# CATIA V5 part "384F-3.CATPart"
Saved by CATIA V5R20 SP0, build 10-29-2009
Part number: 384F-3
Source: Unknown
Property "ARTICLENO": "384F-3"
Property "BOMINFO": "384F-3"
Property "CODE": "384F-3"
Property "CREATOR": "CADENAS GmbH"
Property "D1": "28.000"
Property "D2": "38.000"
Property "ELASTOMER": "Ø125-Ø140"
Property "K": "24.000"
Property "L": "100.000"
Property "L1": "15.000"
Property "L2": "45.000"
Property "LINA": "384F-3"
Property "M": "20.000"
Property "NB": "384F-3"
Property "NBSYN": "$CODE."
Property "NN": "384F"
Property "NT": "Pin for Elastomer Springs"
Property "R": "5.000"
Property "SUPPLIER": "CF"
Property "SW": "10.000"
Bounding box of the stored display mesh (mm): x -17.782 to 17.782, y 0 to 100, z -17.965 to 17.965
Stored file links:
  C:\Users\Raffaele\Desktop\3D X SITO CF\384F\GSB_OILLESS_M31102020100\CATIAV5\384F-3.CATPart
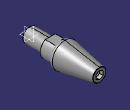
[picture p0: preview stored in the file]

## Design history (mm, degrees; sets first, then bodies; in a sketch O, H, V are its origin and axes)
Body1 "Geometry.1" (main body)
  Solid1 "384F-3.catpart": solid without history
